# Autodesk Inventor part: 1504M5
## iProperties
Shininess: 80.0
Length Units: 11269
Angle Units: 11279
Time Units: 11290
Mass Units: 11284
Length Display Precision: 3
Angle Display Precision: 2
Compacted: True
Company: Pneumax S.p.A.
Part Number: 1504M5
Material: Default
Description: ASTA+ANELLO GIREVOLE Ø4 M5
Document SubType Name: Modellazione
Catalog Web Link: www.pneumaxspa.com
Density: 1.59
Volumn: 0.8648857994912436
Area: 17.092995283760587
PropertySet Name: Model Information
Control State: 0
Master: False
Checked Out: False
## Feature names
1. Revolution6
2. Rivoluzione7 [Revolution]
3. Smusso10 [Chamfer]
4. Foro7 [Hole]
5. Estrusione11 [Extrusion]
6. Foro6 [Hole]
7. Foro8 [Hole]
